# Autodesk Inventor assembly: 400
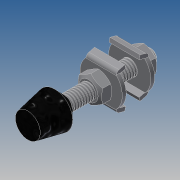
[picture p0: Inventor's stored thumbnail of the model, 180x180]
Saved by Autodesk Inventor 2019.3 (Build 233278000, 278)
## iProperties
Created: 2017-11
Part Number: 400
Material: Ogólny
Document SubType Name: Assembly
Designer: Admin
Author: Admin
Revision Number: ÈÎºÎ
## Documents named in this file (4)
- E:\SERWER_ZAPAS\MODELE brakujace\brakujące stepy_08012019\CH-13007-SM\400.iam
- E:\SERWER_ZAPAS\MODELE brakujace\brakujące stepy_08012019\CH-13007-SM\CH-FW-516.ipt
- E:\SERWER_ZAPAS\MODELE brakujace\brakujące stepy_08012019\CH-13007-SM\CH-FC-56212 Nut.ipt
- E:\SERWER_ZAPAS\MODELE brakujace\brakujące stepy_08012019\CH-13007-SM\CH-FC-56212 SPINDLE SUPPLIED.ipt
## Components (5 placed, 5 different names)
1. CH-FW-516_11 — Zestawiające:2, Zestawiające:3, Zestawiające:4, Równoległe:2
2. CH-FW-516_12 — Zestawiające:4, Równoległe:2, Zestawiające:5, Zestawiające:7
3. CH-FC-56212 Nut_13 — Równoległe:1, Zestawiające:1, Zestawiające:3
4. CH-FC-56212 SPINDLE SUPPLIED_14 — Równoległe:1, Zestawiające:1, Zestawiające:2, Zestawiające:5, Zestawiające:6
5. CH-FC-56212 Nut_15 — Zestawiające:6, Zestawiające:7
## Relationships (9: Mate 7, Flush 2)
- Równoległe:1 [Flush]: CH-FC-56212 Nut_13 ↔ CH-FC-56212 SPINDLE SUPPLIED_14
- Zestawiające:1 [Mate]: CH-FC-56212 Nut_13 ↔ CH-FC-56212 SPINDLE SUPPLIED_14
- Zestawiające:2 [Mate]: CH-FW-516_11 ↔ CH-FC-56212 SPINDLE SUPPLIED_14
- Zestawiające:3 [Mate]: CH-FW-516_11 ↔ CH-FC-56212 Nut_13
- Zestawiające:4 [Mate]: CH-FW-516_11 ↔ CH-FW-516_12
- Równoległe:2 [Flush]: CH-FW-516_11 ↔ CH-FW-516_12
- Zestawiające:5 [Mate]: CH-FW-516_12 ↔ CH-FC-56212 SPINDLE SUPPLIED_14
- Zestawiające:6 [Mate]: CH-FC-56212 SPINDLE SUPPLIED_14 ↔ CH-FC-56212 Nut_15
- Zestawiające:7 [Mate]: CH-FW-516_12 ↔ CH-FC-56212 Nut_15
